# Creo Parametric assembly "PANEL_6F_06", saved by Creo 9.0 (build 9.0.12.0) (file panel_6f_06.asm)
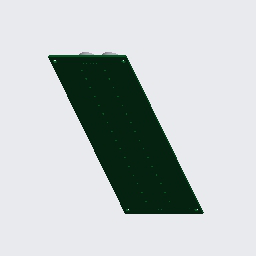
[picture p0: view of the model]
Units: millimeter Newton Second (mmNs); MM, TONNE, SECS

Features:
  1. coordinate system "PANEL_6F_06"
  2. imported feature "Import Feature id 4"
  3. component "PCB_6F"
  4. component "TX_6F_T1"
  5. component "TX_6F_T1"
  6. component "TX_6F_T1"
  7. component "TX_6F_T1"
  8. component "TX_6F_T1"
  9. component "TX_6F_T1"
  10. component "TX_6F_T1"
  11. component "TX_6F_T1"
  12. component "TX_6F_T1"
  13. component "TX_6F_T1"
  14. component "TX_6F_T1"
  15. component "TX_6F_T1"
  16. component "TX_6F_T1"
  17. component "TX_6F_T1"
  18. component "TX_6F_T1"
  19. component "TX_6F_T1"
